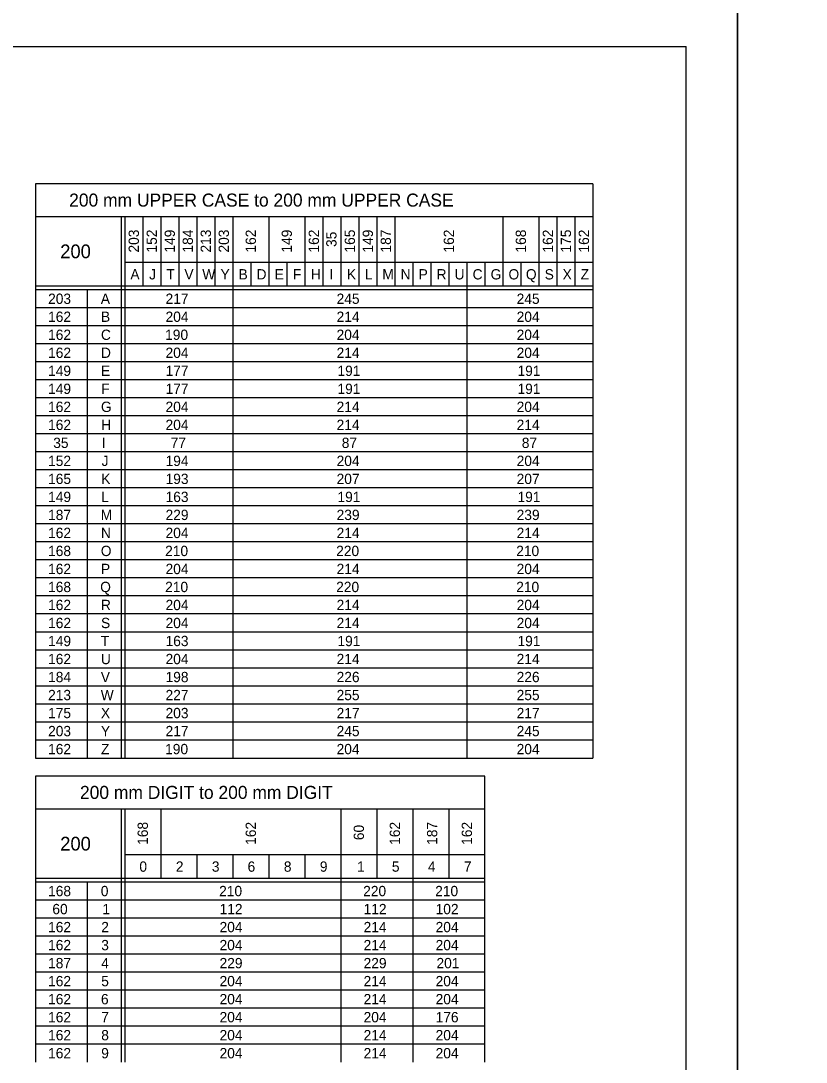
# Model space of a CAD drawing. Extents: x 637580 to 641849, y 297270 to 299646.
# Drawn here: x 638212.3 to 638441.3, y 297552.6 to 297856.1 of the extents above; entities that cross this region are included whole.
import ezdxf

# ---------------------------------------------------------------- set-up
doc = ezdxf.new("R2010")
doc.units = 0
for name, color, linetype in [('1', 7, 'Continuous'), ('2', 7, 'Continuous'), ('XCS-GRID-HVGL', 7, 'Continuous')]:
    doc.layers.add(name, color=color, linetype=linetype)

msp = doc.modelspace()

# ---------------------------------------------------------------- linework, layer by layer
at = {"layer": '1'}
for p in [(637620.31, 297848.63), (638406.31, 297284.63)]:
    msp.add_line(p, (638406.31, 297848.63), dxfattribs=at)
at = {"layer": '2'}
for p, q in [((638379.11, 297808.63), (638216.61, 297808.63)), ((638216.61, 297808.63), (638216.61, 297641.25)), ((638379.11, 297808.63), (638379.11, 297641.25)), ((638216.61, 297799.13), (638379.11, 297799.13)), ((638241.61, 297799.13), (638241.61, 297641.25)), ((638242.61, 297799.13), (638242.61, 297641.25)), ((638247.86, 297799.13), (638247.86, 297778.75)), ((638253.11, 297799.13), (638253.11, 297778.75)), ((638258.36, 297799.13), (638258.36, 297778.75)), ((638263.61, 297799.13), (638263.61, 297778.75)), ((638268.86, 297799.13), (638268.86, 297778.75)), ((638274.11, 297799.13), (638274.11, 297641.25)), ((638284.61, 297799.13), (638284.61, 297778.75)), ((638295.11, 297799.13), (638295.11, 297778.75)), ((638300.36, 297799.13), (638300.36, 297778.75)), ((638305.61, 297799.13), (638305.61, 297778.75)), ((638310.86, 297799.13), (638310.86, 297778.75)), ((638316.11, 297799.13), (638316.11, 297778.75)), ((638321.36, 297799.13), (638321.36, 297778.75)), ((638352.86, 297799.13), (638352.86, 297778.75)), ((638363.36, 297799.13), (638363.36, 297778.75)), ((638368.61, 297799.13), (638368.61, 297778.75)), ((638373.86, 297799.13), (638373.86, 297778.75)), ((638242.61, 297785.75), (638379.11, 297785.75)), ((638279.36, 297785.75), (638279.36, 297778.75)), ((638289.86, 297785.75), (638289.86, 297778.75)), ((638326.61, 297785.75), (638326.61, 297778.75)), ((638331.86, 297785.75), (638331.86, 297778.75)), ((638337.11, 297785.75), (638337.11, 297778.75)), ((638337.11, 297785.75), (638337.11, 297778.75)), ((638342.36, 297785.75), (638342.36, 297641.25)), ((638347.61, 297785.75), (638347.61, 297778.75)), ((638358.11, 297785.75), (638358.11, 297778.75)), ((638379.11, 297778.75), (638216.61, 297778.75)), ((638379.11, 297777.75), (638216.61, 297777.75)), ((638231.61, 297777.75), (638231.61, 297641.25)), ((638379.11, 297772.5), (638216.61, 297772.5)), ((638379.11, 297767.25), (638216.61, 297767.25)), ((638379.11, 297762), (638216.61, 297762)), ((638379.11, 297756.75), (638216.61, 297756.75)), ((638379.11, 297751.5), (638216.61, 297751.5)), ((638379.11, 297746.25), (638216.61, 297746.25)), ((638379.11, 297741), (638216.61, 297741)), ((638379.11, 297735.75), (638216.61, 297735.75)), ((638379.11, 297730.5), (638216.61, 297730.5)), ((638379.11, 297725.25), (638216.61, 297725.25)), ((638379.11, 297720), (638216.61, 297720)), ((638379.11, 297714.75), (638216.61, 297714.75)), ((638379.11, 297709.5), (638216.61, 297709.5)), ((638379.11, 297704.25), (638216.61, 297704.25)), ((638379.11, 297699), (638216.61, 297699)), ((638379.11, 297693.75), (638216.61, 297693.75)), ((638379.11, 297688.5), (638216.61, 297688.5)), ((638379.11, 297683.25), (638216.61, 297683.25)), ((638379.11, 297678), (638216.61, 297678)), ((638379.11, 297672.75), (638216.61, 297672.75)), ((638379.11, 297667.5), (638216.61, 297667.5)), ((638379.11, 297662.25), (638216.61, 297662.25)), ((638379.11, 297657), (638216.61, 297657)), ((638379.11, 297651.75), (638216.61, 297651.75)), ((638379.11, 297646.5), (638216.61, 297646.5)), ((638216.61, 297641.25), (638216.61, 297641.25)), ((638216.61, 297641.25), (638379.11, 297641.25)), ((638347.61, 297636), (638216.61, 297636)), ((638216.61, 297636), (638216.61, 297552.63)), ((638347.61, 297552.63), (638347.61, 297636)), ((638216.61, 297626.5), (638347.61, 297626.5)), ((638241.61, 297626.5), (638241.61, 297552.63)), ((638242.61, 297626.5), (638242.61, 297552.63)), ((638253.11, 297626.5), (638253.11, 297606.13)), ((638305.61, 297626.5), (638305.61, 297552.63)), ((638316.11, 297626.5), (638316.11, 297606.13)), ((638326.61, 297626.5), (638326.61, 297552.63)), ((638337.11, 297626.5), (638337.11, 297606.13)), ((638242.61, 297613.13), (638347.61, 297613.13)), ((638263.61, 297613.13), (638263.61, 297606.13)), ((638274.11, 297613.13), (638274.11, 297606.13)), ((638284.61, 297613.13), (638284.61, 297606.13)), ((638295.11, 297613.13), (638295.11, 297606.13)), ((638347.61, 297606.13), (638216.61, 297606.13)), ((638347.61, 297605.13), (638216.61, 297605.13)), ((638231.61, 297605.13), (638231.61, 297552.63)), ((638347.61, 297599.88), (638216.61, 297599.88)), ((638347.61, 297594.63), (638216.61, 297594.63)), ((638347.61, 297589.38), (638216.61, 297589.38)), ((638347.61, 297584.13), (638216.61, 297584.13)), ((638347.61, 297578.88), (638216.61, 297578.88)), ((638347.61, 297573.63), (638216.61, 297573.63)), ((638347.61, 297568.38), (638216.61, 297568.38)), ((638347.61, 297563.13), (638216.61, 297563.13)), ((638347.61, 297557.88), (638216.61, 297557.88))]:
    msp.add_line(p, q, dxfattribs=at)
at = {"layer": 'XCS-GRID-HVGL'}
for points in [[(637580.31, 297863.63), (638421.31, 297863.63), (638421.31, 297269.63), (637580.31, 297269.63)], [(638421.31, 297863.63), (639262.31, 297863.63), (639262.31, 297269.63), (638421.31, 297269.63)]]:
    msp.add_lwpolyline(points, close=True, dxfattribs=at)

# ---------------------------------------------------------------- texts
at = {"layer": '2'}
for s, height, p in [('200 mm UPPER CASE to 200 mm UPPER CASE', 3.8, (638226.4, 297801.98)), ('200', 4, (638223.8, 297786.94)), ('A', 3, (638244.26, 297780.75)), ('J', 3, (638249.74, 297780.75)), ('T', 3, (638254.74, 297780.75)), ('V', 3, (638260.01, 297780.75)), ('W', 3, (638265.23, 297780.75)), ('Y', 3, (638270.54, 297780.75)), ('B', 3, (638275.8, 297780.75)), ('D', 3, (638281.05, 297780.75)), ('E', 3, (638286.32, 297780.75)), ('F', 3, (638291.62, 297780.75)), ('H', 3, (638296.89, 297780.75)), ('I', 3, (638302.3, 297780.75)), ('K', 3, (638307.39, 297780.75)), ('L', 3, (638312.64, 297780.75)), ('M', 3, (638317.73, 297780.75)), ('N', 3, (638323.05, 297780.75)), ('P', 3, (638328.3, 297780.75)), ('R', 3, (638333.55, 297780.75)), ('U', 3, (638338.79, 297780.75)), ('C', 3, (638344.05, 297780.75)), ('G', 3, (638349.3, 297780.75)), ('O', 3, (638354.51, 297780.75)), ('Q', 3, (638359.58, 297780.75)), ('S', 3, (638365.07, 297780.75)), ('X', 3, (638370.29, 297780.75)), ('Z', 3, (638375.55, 297780.75)), ('203', 3, (638220.26, 297773.63)), ('A', 3, (638235.63, 297773.63)), ('217', 3, (638254.51, 297773.63)), ('245', 3, (638304.39, 297773.63)), ('245', 3, (638356.89, 297773.63)), ('162', 3, (638220.26, 297768.38)), ('B', 3, (638235.68, 297768.38)), ('204', 3, (638254.51, 297768.38)), ('214', 3, (638304.39, 297768.38)), ('204', 3, (638356.89, 297768.38)), ('162', 3, (638220.26, 297763.13)), ('C', 3, (638235.68, 297763.13)), ('190', 3, (638254.39, 297763.13)), ('204', 3, (638304.39, 297763.13)), ('204', 3, (638356.89, 297763.13)), ('162', 3, (638220.26, 297757.88)), ('204', 3, (638254.51, 297757.88)), ('214', 3, (638304.39, 297757.88)), ('204', 3, (638356.89, 297757.88)), ('D', 3, (638235.68, 297757.88)), ('149', 3, (638220.26, 297752.63)), ('E', 3, (638235.69, 297752.63)), ('177', 3, (638254.51, 297752.63)), ('191', 3, (638304.64, 297752.63)), ('191', 3, (638357.14, 297752.63)), ('149', 3, (638220.26, 297747.38)), ('F', 3, (638235.75, 297747.38)), ('177', 3, (638254.51, 297747.38)), ('191', 3, (638304.64, 297747.38)), ('191', 3, (638357.14, 297747.38)), ('162', 3, (638220.26, 297742.13)), ('G', 3, (638235.68, 297742.13)), ('204', 3, (638254.51, 297742.13)), ('214', 3, (638304.39, 297742.13)), ('204', 3, (638356.89, 297742.13)), ('162', 3, (638220.26, 297736.88)), ('H', 3, (638235.76, 297736.88)), ('204', 3, (638254.51, 297736.88)), ('214', 3, (638304.39, 297736.88)), ('214', 3, (638356.89, 297736.88)), ('35', 3, (638221.76, 297731.63)), ('I', 3, (638235.93, 297731.63)), ('77', 3, (638256.01, 297731.63)), ('87', 3, (638305.89, 297731.63)), ('87', 3, (638358.39, 297731.63)), ('152', 3, (638220.26, 297726.38)), ('J', 3, (638235.87, 297726.38)), ('194', 3, (638254.51, 297726.38)), ('204', 3, (638304.39, 297726.38)), ('204', 3, (638356.89, 297726.38)), ('165', 3, (638220.26, 297721.13)), ('K', 3, (638235.76, 297721.13)), ('193', 3, (638254.51, 297721.13)), ('207', 3, (638304.39, 297721.13)), ('207', 3, (638356.89, 297721.13)), ('149', 3, (638220.26, 297715.88)), ('L', 3, (638235.76, 297715.88)), ('163', 3, (638254.51, 297715.88)), ('191', 3, (638304.64, 297715.88)), ('191', 3, (638357.14, 297715.88)), ('187', 3, (638220.26, 297710.63)), ('M', 3, (638235.61, 297710.63)), ('229', 3, (638254.51, 297710.63)), ('239', 3, (638304.39, 297710.63)), ('239', 3, (638356.89, 297710.63)), ('162', 3, (638220.26, 297705.38)), ('N', 3, (638235.68, 297705.38)), ('204', 3, (638254.51, 297705.38)), ('214', 3, (638304.39, 297705.38)), ('214', 3, (638356.89, 297705.38)), ('168', 3, (638220.26, 297700.13)), ('O', 3, (638235.63, 297700.13)), ('210', 3, (638254.39, 297700.13)), ('220', 3, (638304.26, 297700.13)), ('210', 3, (638356.76, 297700.13)), ('162', 3, (638220.26, 297694.88)), ('P', 3, (638235.68, 297694.88)), ('204', 3, (638254.51, 297694.88)), ('214', 3, (638304.39, 297694.88)), ('204', 3, (638356.89, 297694.88)), ('168', 3, (638220.26, 297689.63)), ('Q', 3, (638235.45, 297689.63)), ('210', 3, (638254.39, 297689.63)), ('220', 3, (638304.26, 297689.63)), ('210', 3, (638356.76, 297689.63)), ('162', 3, (638220.26, 297684.38)), ('R', 3, (638235.68, 297684.38)), ('204', 3, (638254.51, 297684.38)), ('214', 3, (638304.39, 297684.38)), ('204', 3, (638356.89, 297684.38)), ('162', 3, (638220.26, 297679.13)), ('S', 3, (638235.69, 297679.13)), ('204', 3, (638254.51, 297679.13)), ('214', 3, (638304.39, 297679.13)), ('204', 3, (638356.89, 297679.13)), ('149', 3, (638220.26, 297673.88)), ('T', 3, (638235.62, 297673.88)), ('163', 3, (638254.51, 297673.88)), ('191', 3, (638304.64, 297673.88)), ('191', 3, (638357.14, 297673.88)), ('162', 3, (638220.26, 297668.63)), ('U', 3, (638235.67, 297668.63)), ('204', 3, (638254.51, 297668.63)), ('214', 3, (638304.39, 297668.63)), ('214', 3, (638356.89, 297668.63)), ('184', 3, (638220.26, 297663.38)), ('V', 3, (638235.63, 297663.38)), ('198', 3, (638254.51, 297663.38)), ('226', 3, (638304.39, 297663.38)), ('226', 3, (638356.89, 297663.38)), ('213', 3, (638220.26, 297658.13)), ('W', 3, (638235.61, 297658.13)), ('227', 3, (638254.51, 297658.13)), ('255', 3, (638304.39, 297658.13)), ('255', 3, (638356.89, 297658.13)), ('175', 3, (638220.26, 297652.88)), ('X', 3, (638235.67, 297652.88)), ('203', 3, (638254.51, 297652.88)), ('217', 3, (638304.39, 297652.88)), ('217', 3, (638356.89, 297652.88)), ('203', 3, (638220.26, 297647.63)), ('Y', 3, (638235.67, 297647.63)), ('217', 3, (638254.51, 297647.63)), ('245', 3, (638304.39, 297647.63)), ('245', 3, (638356.89, 297647.63)), ('162', 3, (638220.26, 297642.38)), ('Z', 3, (638235.68, 297642.38)), ('190', 3, (638254.39, 297642.38)), ('204', 3, (638304.39, 297642.38)), ('204', 3, (638356.89, 297642.38)), ('200 mm DIGIT to 200 mm DIGIT', 3.8, (638229.56, 297629.35)), ('200', 4, (638223.8, 297614.31)), ('0', 3, (638246.88, 297608.13)), ('2', 3, (638257.51, 297608.13)), ('3', 3, (638268.01, 297608.13)), ('6', 3, (638278.43, 297608.13)), ('8', 3, (638289.01, 297608.13)), ('9', 3, (638299.5, 297608.13)), ('1', 3, (638310.35, 297608.13)), ('5', 3, (638320.51, 297608.13)), ('4', 3, (638331.01, 297608.13)), ('7', 3, (638341.51, 297608.13)), ('168', 3, (638220.26, 297601)), ('0', 3, (638235.63, 297601)), ('210', 3, (638270.13, 297601)), ('220', 3, (638312.13, 297601)), ('210', 3, (638333.13, 297601)), ('60', 3, (638221.51, 297595.75)), ('1', 3, (638236.1, 297595.75)), ('112', 3, (638270.26, 297595.75)), ('112', 3, (638312.26, 297595.75)), ('102', 3, (638333.26, 297595.75)), ('162', 3, (638220.26, 297590.5)), ('2', 3, (638235.76, 297590.5)), ('204', 3, (638270.26, 297590.5)), ('214', 3, (638312.26, 297590.5)), ('204', 3, (638333.26, 297590.5)), ('162', 3, (638220.26, 297585.25)), ('3', 3, (638235.76, 297585.25)), ('204', 3, (638270.26, 297585.25)), ('214', 3, (638312.26, 297585.25)), ('204', 3, (638333.26, 297585.25)), ('187', 3, (638220.26, 297580)), ('4', 3, (638235.76, 297580)), ('229', 3, (638270.26, 297580)), ('229', 3, (638312.26, 297580)), ('201', 3, (638333.51, 297580)), ('162', 3, (638220.26, 297574.75)), ('5', 3, (638235.76, 297574.75)), ('204', 3, (638270.26, 297574.75)), ('214', 3, (638312.26, 297574.75)), ('204', 3, (638333.26, 297574.75)), ('162', 3, (638220.26, 297569.5)), ('6', 3, (638235.68, 297569.5)), ('204', 3, (638270.26, 297569.5)), ('214', 3, (638312.26, 297569.5)), ('204', 3, (638333.26, 297569.5)), ('162', 3, (638220.26, 297564.25)), ('7', 3, (638235.76, 297564.25)), ('204', 3, (638270.26, 297564.25)), ('204', 3, (638312.26, 297564.25)), ('176', 3, (638333.26, 297564.25)), ('162', 3, (638220.26, 297559)), ('8', 3, (638235.76, 297559)), ('204', 3, (638270.26, 297559)), ('214', 3, (638312.26, 297559)), ('204', 3, (638333.26, 297559)), ('162', 3, (638220.26, 297553.75)), ('9', 3, (638235.75, 297553.75)), ('204', 3, (638270.26, 297553.75)), ('214', 3, (638312.26, 297553.75)), ('204', 3, (638333.26, 297553.75))]:
    msp.add_text(s, height=height, dxfattribs=at).set_placement(p)
for s, p in [('203', (638246.74, 297788.59)), ('152', (638251.99, 297788.59)), ('149', (638257.24, 297788.58)), ('184', (638262.49, 297788.59)), ('213', (638267.74, 297788.59)), ('203', (638272.99, 297788.59)), ('162', (638280.86, 297788.59)), ('149', (638291.36, 297788.58)), ('162', (638299.24, 297788.59)), ('35', (638304.36, 297790.21)), ('165', (638309.74, 297788.59)), ('149', (638314.99, 297788.58)), ('187', (638320.24, 297788.59)), ('162', (638338.61, 297788.59)), ('168', (638359.61, 297788.59)), ('162', (638367.49, 297788.59)), ('175', (638372.74, 297788.59)), ('162', (638377.99, 297788.59)), ('168', (638249.36, 297615.96)), ('162', (638280.86, 297615.96)), ('60', (638312.36, 297617.33)), ('162', (638322.86, 297615.96)), ('187', (638333.74, 297615.96)), ('162', (638343.86, 297615.96))]:
    msp.add_text(s, height=3, rotation=90, dxfattribs=at).set_placement(p)

doc.saveas('drawing.dxf')
